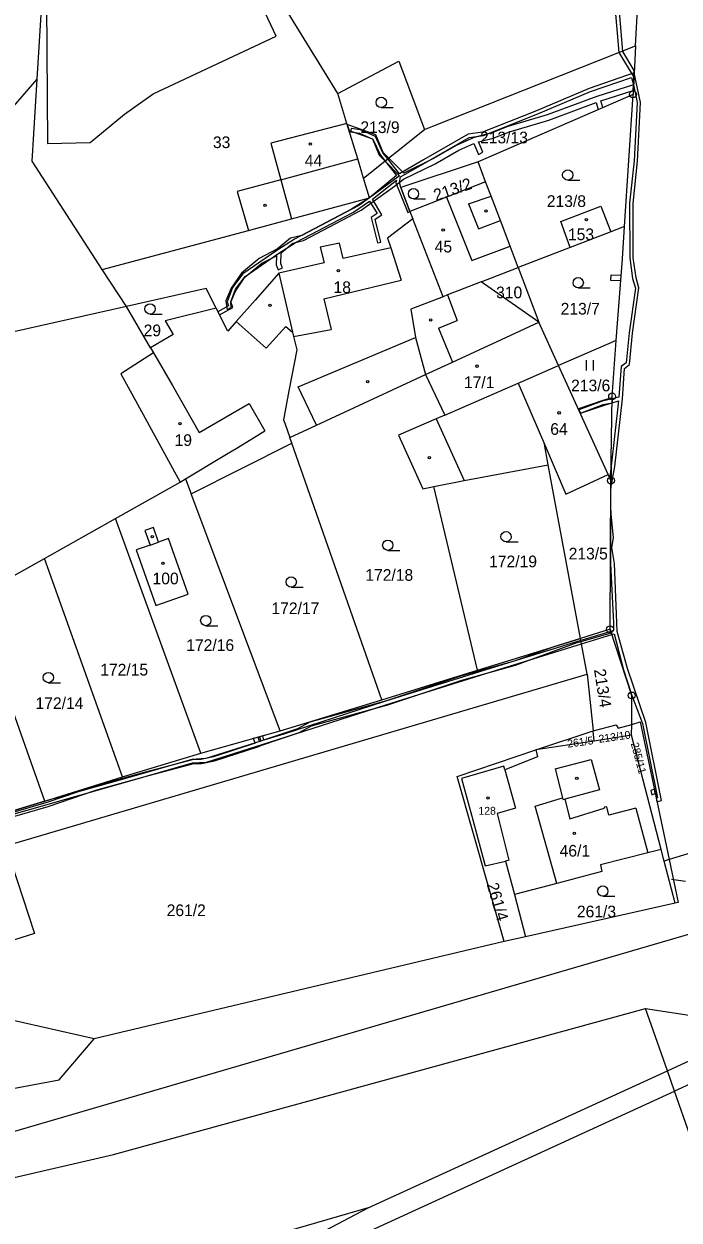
# Model space of a CAD drawing. Extents: x -779723 to -777378, y -1011169 to -1009297.
# Drawn here: x -779040.4 to -778945.2, y -1010475.7 to -1010301.7 of the extents above; entities that cross this region are included whole.
import ezdxf

# ---------------------------------------------------------------- set-up
doc = ezdxf.new("R2010")
doc.units = 0
for name, color, linetype in [('Hranice parcel', 7, 'Continuous'), ('Parcelní čísla', 7, 'Continuous'), ('Pop  PČ popisy', 7, 'Continuous'), ('Poz předměty', 7, 'Continuous'), ('Vnitřní kresba', 7, 'Continuous'), ('Věcná břemena k části', 7, 'Continuous'), ('Značky bodu BP', 7, 'Continuous'), ('Značky budov', 7, 'Continuous'), ('Značky kultur', 7, 'Continuous')]:
    doc.layers.add(name, color=color, linetype=linetype)

msp = doc.modelspace()

# ---------------------------------------------------------------- linework, layer by layer
at = {"layer": 'Hranice parcel'}
for p, q in [((-779038.46, -1010309.75), (-779037.78, -1010298.79)), ((-778951.52, -1010304.9), (-778951.89, -1010311.98)), ((-778993.45, -1010316.22), (-778994.79, -1010311.83)), ((-778951.89, -1010311.98), (-778974.4, -1010321.81)), ((-778953.14, -1010331.19), (-778951.89, -1010311.98)), ((-778991.02, -1010324.17), (-778982.17, -1010317.08)), ((-778973.3, -1010324.71), (-778974.4, -1010321.81)), ((-778962.38, -1010330.47), (-778956.54, -1010328.23)), ((-778956.54, -1010328.23), (-778955.13, -1010331.96)), ((-778984.3, -1010328.99), (-778983.88, -1010330.06)), ((-778979.48, -1010341.4), (-778983.88, -1010330.06)), ((-778961.01, -1010334.24), (-778962.38, -1010330.47)), ((-779028.99, -1010337.46), (-779007.73, -1010331.75)), ((-778955.13, -1010331.96), (-778961.01, -1010334.24)), ((-778953.14, -1010331.19), (-778955.13, -1010331.96)), ((-778961.01, -1010334.24), (-778968.56, -1010337.17)), ((-779025.5, -1010342.84), (-779028.99, -1010337.46)), ((-778973.94, -1010339.25), (-778968.56, -1010337.17)), ((-778968.56, -1010337.17), (-778965.56, -1010345.08)), ((-778965.56, -1010345.08), (-778973.94, -1010339.25)), ((-779025.5, -1010342.84), (-779071.49, -1010353.21)), ((-779021.98, -1010348.86), (-779025.5, -1010342.84)), ((-778962.69, -1010351.41), (-778965.56, -1010345.08)), ((-778954.32, -1010347.77), (-778962.69, -1010351.41)), ((-778955.49, -1010367.27), (-778962.69, -1010351.41)), ((-778982.04, -1010352.73), (-778979.24, -1010358.61)), ((-779001.48, -1010362.68), (-779001.76, -1010361.88)), ((-779016.08, -1010370.08), (-779001.48, -1010362.68)), ((-778988.37, -1010400.03), (-779001.48, -1010362.68)), ((-778959.52, -1010391.1), (-778964.2, -1010365.84)), ((-779027.09, -1010373.66), (-779017.69, -1010368.36)), ((-778955.1, -1010368.13), (-778955.49, -1010367.27)), ((-778955.22, -1010389.77), (-778955.1, -1010368.13)), ((-779003.14, -1010404.53), (-779016.08, -1010370.08)), ((-778974.46, -1010395.73), (-778980.82, -1010369)), ((-779037.39, -1010379.46), (-779027.09, -1010373.66)), ((-779014.66, -1010407.79), (-779027.09, -1010373.66)), ((-779047.78, -1010385.31), (-779037.39, -1010379.46)), ((-779026.05, -1010411.22), (-779037.39, -1010379.46)), ((-779037.35, -1010414.74), (-779047.78, -1010385.31)), ((-778955.22, -1010389.77), (-778959.52, -1010391.1)), ((-778974.46, -1010395.73), (-778959.52, -1010391.1)), ((-778958.54, -1010396.31), (-778959.52, -1010391.1)), ((-779043.02, -1010421.24), (-778958.54, -1010396.31)), ((-778988.37, -1010400.03), (-778974.46, -1010395.73)), ((-778958.54, -1010396.31), (-778957.7, -1010404.52)), ((-779003.14, -1010404.53), (-778988.37, -1010400.03)), ((-778952.09, -1010405.18), (-778952.08, -1010403.6)), ((-779014.66, -1010407.79), (-779003.14, -1010404.53)), ((-778966, -1010407.32), (-778957.7, -1010404.52)), ((-778957.55, -1010406.02), (-778957.7, -1010404.52)), ((-778952.09, -1010405.18), (-778957.55, -1010406.02)), ((-778947.8, -1010421.79), (-778952.09, -1010405.18)), ((-778957.55, -1010406.02), (-778966, -1010407.32)), ((-779026.05, -1010411.22), (-779014.66, -1010407.79)), ((-779037.35, -1010414.74), (-779026.05, -1010411.22)), ((-779048.8, -1010418.22), (-779037.35, -1010414.74)), ((-778947.37, -1010423.47), (-778947.8, -1010421.79)), ((-778970.41, -1010423.47), (-778969.13, -1010428.34)), ((-778946.64, -1010423.24), (-778947.37, -1010423.47)), ((-778945.78, -1010429.62), (-778947.37, -1010423.47)), ((-778969.13, -1010428.34), (-778967.51, -1010434.5)), ((-778945.78, -1010429.62), (-778967.51, -1010434.5)), ((-778967.51, -1010434.5), (-778970.59, -1010435.19)), ((-778970.59, -1010435.19), (-779030.17, -1010449.35)), ((-778950.06, -1010444.91), (-778942.45, -1010446.06)), ((-778946.9, -1010453.97), (-778950.06, -1010444.91)), ((-778990.37, -1010473.89), (-778946.9, -1010453.97)), ((-778945.86, -1010456.94), (-778946.9, -1010453.97)), ((-778927.24, -1010510.3), (-778945.86, -1010456.94)), ((-779003.19, -1010480.64), (-778990.37, -1010473.89))]:
    msp.add_line(p, q, dxfattribs=at)
for points in [[(-778951.52, -1010304.9), (-778950.58, -1010287.37), (-778950.58, -1010286.9), (-778950.34, -1010251.89), (-778953.35, -1010232.46), (-778955.45, -1010215), (-778962.68, -1010202.09), (-778972.6, -1010193.75), (-778987.54, -1010189.4), (-778999.84, -1010191.68), (-779009.45, -1010195.21), (-779017.34, -1010206.13), (-779023.92, -1010222.47), (-779024.96, -1010244.9), (-779026.78, -1010253.95)], [(-779037.1, -1010298.8), (-779036.94, -1010319.12), (-779030.77, -1010318.99), (-779025.76, -1010314.84), (-779021.61, -1010311.89), (-779003.74, -1010303.52), (-779004.9, -1010301.02), (-779009.89, -1010290.29)], [(-778994.79, -1010311.83), (-779008.43, -1010289.59), (-779009.89, -1010290.29)], [(-778982.17, -1010317.08), (-778980.98, -1010316.61), (-778951.52, -1010304.9)], [(-778994.79, -1010311.83), (-778985.9, -1010307.16), (-778982.17, -1010317.08)], [(-779058.85, -1010331.38), (-779053.49, -1010327.09), (-779038.46, -1010309.75)], [(-779028.99, -1010337.46), (-779039.2, -1010321.7), (-779038.46, -1010309.75)], [(-778993.45, -1010316.22), (-779004.53, -1010319.08), (-779003.07, -1010324.38), (-779009.39, -1010326.11), (-779007.73, -1010331.75)], [(-778991.02, -1010324.17), (-778991.89, -1010321.33), (-778993.45, -1010316.22)], [(-778974.4, -1010321.81), (-778985.64, -1010325.53), (-778984.3, -1010328.99)], [(-779007.73, -1010331.75), (-779001.5, -1010330.08), (-778990.15, -1010327.02), (-778991.02, -1010324.17)], [(-778973.3, -1010324.71), (-778978.98, -1010326.92), (-778984.3, -1010328.99)], [(-778968.56, -1010337.17), (-778969.74, -1010334.07), (-778971.16, -1010330.34), (-778972.52, -1010326.77), (-778973.3, -1010324.71)], [(-778983.88, -1010330.06), (-778987.54, -1010332.88), (-778987.09, -1010334.27), (-778994.02, -1010335.85), (-778994.52, -1010333.62), (-778997.34, -1010334.21), (-778996.76, -1010336.48), (-779003.36, -1010337.99)], [(-778954.32, -1010347.77), (-778953.44, -1010335.87), (-778953.14, -1010331.19)], [(-779003.36, -1010337.99), (-779006.8, -1010341.91), (-779009.52, -1010345.02), (-779010.76, -1010346.43), (-779012.47, -1010343.06)], [(-779003.36, -1010337.99), (-779001.36, -1010346.54), (-779001.2, -1010347.2), (-779000.74, -1010349.14), (-779001.87, -1010355.1), (-779002.67, -1010359.29), (-779002.49, -1010359.8), (-779001.76, -1010361.88)], [(-778973.94, -1010339.25), (-778977.19, -1010340.51), (-778978.84, -1010341.15), (-778979.48, -1010341.4)], [(-779012.47, -1010343.06), (-779013.91, -1010340.22), (-779025.5, -1010342.84)], [(-778979.48, -1010341.4), (-778984.19, -1010343.23), (-778983.47, -1010347.31), (-778982.04, -1010352.73)], [(-779012.47, -1010343.06), (-779019.86, -1010344.89), (-779018.7, -1010346.92), (-779021.98, -1010348.86)], [(-778955.1, -1010368.13), (-778954.92, -1010355.9), (-778954.32, -1010347.77)], [(-779021.98, -1010348.86), (-779021.56, -1010349.58), (-779026.3, -1010352.61), (-779023.89, -1010357.02), (-779017.69, -1010368.36)], [(-778979.24, -1010358.61), (-778968.59, -1010353.97), (-778967.89, -1010353.67), (-778962.69, -1010351.41)], [(-779001.76, -1010361.88), (-778997.87, -1010360.08), (-778982.04, -1010352.73)], [(-778979.24, -1010358.61), (-778980.51, -1010359.16), (-778985.96, -1010361.53), (-778982.41, -1010369.32), (-778980.82, -1010369)], [(-778964.2, -1010365.84), (-778964.75, -1010362.86), (-778961.63, -1010370.1), (-778955.49, -1010367.27)], [(-778980.82, -1010369), (-778976.43, -1010368.12), (-778964.2, -1010365.84)], [(-779017.69, -1010368.36), (-779016.89, -1010367.91), (-779016.08, -1010370.08)], [(-779022.06, -1010377.52), (-779024.08, -1010378.22), (-779021.2, -1010386.31), (-779016.52, -1010384.66), (-779019.35, -1010376.56), (-779020.82, -1010377.08), (-779021.54, -1010374.98), (-779022.8, -1010375.42), (-779022.06, -1010377.52)], [(-778952.08, -1010403.6), (-778952.07, -1010399.39), (-778955.22, -1010389.77)], [(-778957.7, -1010404.52), (-778954.34, -1010403.64), (-778954.03, -1010404.17), (-778952.08, -1010403.6)], [(-778952.08, -1010403.6), (-778950.86, -1010403.24), (-778946.64, -1010423.24)], [(-778970.59, -1010435.19), (-778977.43, -1010411.17), (-778966, -1010407.32)], [(-778966, -1010407.32), (-778965.76, -1010408.34), (-778970.52, -1010410.2)], [(-778970.52, -1010410.2), (-778970.66, -1010409.66), (-778976.79, -1010411.48), (-778975.16, -1010417.48), (-778973.38, -1010424.16), (-778970.41, -1010423.47)], [(-778970.52, -1010410.2), (-778968.98, -1010415.79), (-778971.61, -1010416.57), (-778969.93, -1010423.36), (-778970.41, -1010423.47)], [(-779043.02, -1010421.24), (-779038.86, -1010434.01), (-779059.85, -1010440.67), (-779063.54, -1010427.85)], [(-778947.8, -1010421.79), (-778949.74, -1010422.28), (-778956.63, -1010424.04), (-778956.41, -1010425.01), (-778962.94, -1010426.72), (-778969.13, -1010428.34)], [(-778934.57, -1010425.53), (-778941.48, -1010421.68), (-778946.64, -1010423.24)], [(-778946.64, -1010423.24), (-778945.31, -1010429.51), (-778945.78, -1010429.62)], [(-779161.4, -1010480.57), (-779135.21, -1010481.09), (-779105.39, -1010479.5), (-779067.56, -1010475.45), (-779027.37, -1010466.13), (-778950.06, -1010444.91)], [(-779030.17, -1010449.35), (-779043.03, -1010446.43), (-779084.08, -1010446.73), (-779168.06, -1010459.43)], [(-779165.75, -1010470.45), (-779127.38, -1010469.51), (-779070.54, -1010461.9), (-779035.24, -1010455.28), (-779030.17, -1010449.35)], [(-778946.9, -1010453.97), (-778941.12, -1010451.33), (-778940.34, -1010454.4), (-778945.86, -1010456.94)], [(-779019.86, -1010492.97), (-778990.5, -1010477.42), (-778945.86, -1010456.94)], [(-778990.37, -1010473.89), (-779005.39, -1010478.26), (-779064.14, -1010491.18), (-779114.77, -1010499.04), (-779160.87, -1010496.55)]]:
    msp.add_lwpolyline(points, dxfattribs=at)
at = {"layer": 'Pop  PČ popisy'}
msp.add_line((-778946.3, -1010426.12), (-778944.25, -1010426.4), dxfattribs=at)
at = {"layer": 'Poz předměty'}
msp.add_line((-779042.85, -1010463.08), (-778940.99, -1010433.26), dxfattribs=at)
at = {"layer": 'Vnitřní kresba'}
for p, q in [((-779003.07, -1010324.38), (-778991.89, -1010321.33)), ((-779003.07, -1010324.38), (-779001.5, -1010330.08)), ((-778978.98, -1010326.92), (-778975.29, -1010336.14)), ((-778975.77, -1010327.87), (-778972.52, -1010326.77)), ((-778975.77, -1010327.87), (-778974.32, -1010331.52)), ((-778974.32, -1010331.52), (-778971.16, -1010330.34)), ((-778975.29, -1010336.14), (-778969.74, -1010334.07)), ((-778987.09, -1010334.27), (-778985.56, -1010339)), ((-778996.79, -1010341.72), (-778985.56, -1010339)), ((-778996.79, -1010341.72), (-778995.73, -1010346.15)), ((-778978.84, -1010341.15), (-778977.42, -1010344.84)), ((-779009.52, -1010345.02), (-779005.2, -1010348.89)), ((-779005.2, -1010348.89), (-779002.31, -1010345.73)), ((-779002.31, -1010345.73), (-779001.36, -1010346.54)), ((-779001.2, -1010347.2), (-778995.73, -1010346.15)), ((-778980.14, -1010345.98), (-778977.42, -1010344.84)), ((-778980.14, -1010345.98), (-778978.1, -1010350.9)), ((-778970.99, -1010347.6), (-778965.56, -1010345.08)), ((-779000.55, -1010354.53), (-778983.47, -1010347.31)), ((-778978.1, -1010350.9), (-778970.99, -1010347.6)), ((-779021.56, -1010349.58), (-779018.79, -1010354.32)), ((-778982.04, -1010352.73), (-778978.1, -1010350.9)), ((-779018.79, -1010354.32), (-779014.92, -1010361.14)), ((-778997.87, -1010360.08), (-779000.55, -1010354.53)), ((-778968.59, -1010353.97), (-778964.75, -1010362.86)), ((-779014.92, -1010361.14), (-779007.64, -1010356.95)), ((-779007.64, -1010356.95), (-779005.36, -1010360.92)), ((-778980.51, -1010359.16), (-778976.43, -1010368.12)), ((-779009.32, -1010363.32), (-779005.36, -1010360.92)), ((-779011.17, -1010364.44), (-779009.32, -1010363.32)), ((-779016.89, -1010367.91), (-779011.17, -1010364.44)), ((-779022.06, -1010377.52), (-779020.82, -1010377.08)), ((-778963.18, -1010410.04), (-778957.95, -1010408.71)), ((-778957.95, -1010408.71), (-778956.78, -1010413.11)), ((-778963.18, -1010410.04), (-778962.15, -1010414.29)), ((-778956.78, -1010413.11), (-778961.8, -1010414.46)), ((-778966.1, -1010415.49), (-778962.15, -1010414.29)), ((-778962.94, -1010426.72), (-778966.1, -1010415.49)), ((-778962.15, -1010414.29), (-778962.09, -1010414.54)), ((-778962.09, -1010414.54), (-778961.8, -1010414.46)), ((-778961.8, -1010414.46), (-778961.07, -1010417.35)), ((-778961.07, -1010417.35), (-778956.08, -1010415.8)), ((-778955.71, -1010415.59), (-778956.1, -1010415.63)), ((-778956.1, -1010415.63), (-778956.08, -1010415.8)), ((-778955.41, -1010416.79), (-778955.71, -1010415.59)), ((-778951.46, -1010415.8), (-778955.41, -1010416.79)), ((-778951.46, -1010415.8), (-778949.74, -1010422.28))]:
    msp.add_line(p, q, dxfattribs=at)
at = {"layer": 'Věcná břemena k části'}
for points in [[(-778950.6, -1010287.72), (-778950.57, -1010286.48), (-778952.33, -1010289.54), (-778954.01, -1010291.89), (-778954.95, -1010294.05), (-778953.94, -1010305.88), (-778951.76, -1010309.46), (-778951.7, -1010308.5), (-778953.36, -1010305.72), (-778954.33, -1010294.15), (-778953.49, -1010292.19), (-778951.83, -1010289.86)], [(-778951.81, -1010310.57), (-778951.72, -1010308.85), (-778958.25, -1010311.12), (-778966.14, -1010314.45), (-778973.74, -1010317.48), (-778975.86, -1010317.76), (-778982.33, -1010321.49), (-778985.82, -1010323.51), (-778987.52, -1010321.36), (-778988.22, -1010320.47), (-778989.32, -1010318.12), (-778991.49, -1010317.14), (-778992.86, -1010316.95), (-778992.92, -1010317.44), (-778991.63, -1010317.62), (-778989.7, -1010318.5), (-778988.64, -1010320.73), (-778987.91, -1010321.68), (-778986.23, -1010323.79), (-778990.15, -1010327.02), (-778992.78, -1010328.66), (-779001.07, -1010333.01), (-779003.64, -1010334.66), (-779008.59, -1010338.09), (-779010.06, -1010340.05), (-779010.83, -1010342.13), (-779010.64, -1010342.73), (-779012.19, -1010343.61), (-779011.96, -1010344.06), (-779010.04, -1010342.97), (-779010.31, -1010342.15), (-779009.62, -1010340.29), (-779008.23, -1010338.45), (-779003.36, -1010335.08), (-779000.81, -1010333.45), (-778992.52, -1010329.1), (-778990.15, -1010327.52), (-778989.05, -1010329.31), (-778989.92, -1010329.88), (-778988.99, -1010333.58), (-778988.51, -1010333.46), (-778989.34, -1010330.1), (-778988.37, -1010329.47), (-778989.74, -1010327.23), (-778986.27, -1010324.46), (-778986.35, -1010324.84), (-778984.59, -1010329.14), (-778984.3, -1010328.99), (-778985.64, -1010325.53), (-778985.83, -1010324.8), (-778985.66, -1010323.99), (-778982.08, -1010321.92), (-778975.7, -1010318.24), (-778973.62, -1010317.96), (-778965.95, -1010314.91), (-778958.07, -1010311.58), (-778952.1, -1010309.51)], [(-778951.81, -1010310.57), (-778951.3, -1010313.18), (-778951.72, -1010321.64), (-778952.39, -1010327.82), (-778952.34, -1010335.76), (-778951.95, -1010338.74), (-778951.55, -1010340.15), (-778952.45, -1010346.64), (-778952.86, -1010351.01), (-778953.6, -1010351.56), (-778953.93, -1010356.01), (-778954.93, -1010356.24), (-778954.93, -1010356.85), (-778953.98, -1010356.53), (-778955.07, -1010366.03), (-778955.07, -1010366.37), (-778955.11, -1010369.23), (-778954.52, -1010366.11), (-778953.44, -1010356.23), (-778953.12, -1010351.82), (-778952.38, -1010351.27), (-778951.96, -1010346.7), (-778951.05, -1010340.11), (-778951.45, -1010338.64), (-778951.85, -1010335.73), (-778951.89, -1010327.84), (-778951.23, -1010321.68), (-778950.8, -1010313.14), (-778951.72, -1010308.85)], [(-778951.86, -1010311.41), (-778951.81, -1010310.57), (-778957.14, -1010312.27), (-778964.34, -1010314.96), (-778970.06, -1010316.64), (-778972.41, -1010317.59), (-778974.95, -1010318.23), (-778977.5, -1010319.37), (-778980.96, -1010321.37), (-778985.2, -1010323.44), (-778987.37, -1010321.25), (-778988.17, -1010320.44), (-778989.23, -1010317.87), (-778993.4, -1010316.38), (-778993.15, -1010317.22), (-778989.75, -1010318.43), (-778988.77, -1010320.8), (-778987.91, -1010321.68), (-778985.82, -1010323.81), (-778986.93, -1010324.67), (-778990.15, -1010327.02), (-778991.73, -1010328.12), (-779000, -1010332.48), (-779001.64, -1010332.9), (-779003.52, -1010334.46), (-779006.18, -1010335.82), (-779008.78, -1010337.99), (-779010.26, -1010340.16), (-779011.03, -1010342.02), (-779010.83, -1010343.3), (-779010.27, -1010342.92), (-779010.32, -1010342.18), (-779009.66, -1010340.6), (-779008.28, -1010338.58), (-779005.81, -1010336.52), (-779003.7, -1010335.44), (-779003.74, -1010336.76), (-779003.45, -1010337.49), (-779002.81, -1010337.18), (-779003.04, -1010336.62), (-779002.99, -1010335.02), (-779001.33, -1010333.63), (-778999.75, -1010333.23), (-778991.39, -1010328.82), (-778986.54, -1010325.33), (-778985.21, -1010324.31), (-778980.65, -1010322.08), (-778977.19, -1010320.11), (-778975, -1010319.12), (-778974.32, -1010320.72), (-778973.7, -1010320.39), (-778974.33, -1010318.9), (-778972.21, -1010318.36), (-778969.83, -1010317.41), (-778964.12, -1010315.73), (-778957.24, -1010313.16), (-778956.93, -1010314.18), (-778956.29, -1010313.9), (-778956.58, -1010312.93)], [(-778953.67, -1010339.03), (-778953.62, -1010338.33), (-778955.13, -1010338.28), (-778955.15, -1010338.98)], [(-778955.91, -1010357.11), (-778954.93, -1010356.85), (-778954.92, -1010356.12), (-778956.11, -1010356.44), (-778959.83, -1010357.7), (-778959.54, -1010358.35)], [(-778954.93, -1010356.85), (-778954.93, -1010356.24), (-778956.37, -1010356.58), (-778959.78, -1010357.83), (-778959.54, -1010358.35), (-778956.23, -1010357.06)], [(-778955.1, -1010368.13), (-778955.07, -1010366.37), (-778955.32, -1010367.66)], [(-778948.41, -1010414.84), (-778947.75, -1010414.66), (-778950.03, -1010403.32), (-778952.7, -1010395.48), (-778954.19, -1010390.08), (-778954.23, -1010388.81), (-778954.6, -1010380.19), (-778954.98, -1010377.89), (-778954.73, -1010376.46), (-778955.12, -1010372.49), (-778955.15, -1010376.44), (-778955.17, -1010380.25), (-778954.72, -1010388.82), (-778954.7, -1010389.94), (-778955.12, -1010390.07), (-778954.97, -1010390.54), (-778954.61, -1010390.43), (-778953.29, -1010395.66), (-778952.07, -1010399.39), (-778950.51, -1010403.45), (-778948.33, -1010414.3), (-778948.52, -1010414.35)], [(-778949.16, -1010413.82), (-778948.67, -1010413.64), (-778948.79, -1010413.04), (-778949.28, -1010413.23)]]:
    msp.add_lwpolyline(points, close=True, dxfattribs=at)
for points in [[(-779046.91, -1010418.45), (-779036.85, -1010415.56), (-779029.92, -1010413.18), (-779022.74, -1010411.18), (-779015.68, -1010409.29), (-779014.6, -1010409.28), (-779012.68, -1010408.91), (-779006.27, -1010406.8), (-779005.94, -1010406.67), (-779000.37, -1010404.78), (-778998.61, -1010403.83), (-778987.53, -1010400.74), (-778976.78, -1010397.17), (-778968.97, -1010394.97), (-778959.99, -1010391.71), (-778959.44, -1010391.55), (-778955.06, -1010390.27), (-778955.22, -1010389.77), (-778959.52, -1010391.1), (-778963.4, -1010392.3), (-778969.15, -1010394.39), (-778976.96, -1010396.59), (-778987.71, -1010400.16), (-778998.83, -1010403.27), (-779000.61, -1010404.22), (-779006.14, -1010406.11), (-779006.37, -1010405.44), (-779007.05, -1010405.64), (-779006.8, -1010406.35), (-779012.84, -1010408.33), (-779014.66, -1010408.68), (-779015.76, -1010408.69), (-779022.9, -1010410.6), (-779030.1, -1010412.6), (-779037.03, -1010414.98), (-779046.65, -1010417.75)], [(-779046.94, -1010418.07), (-779025.61, -1010411.99), (-779015.88, -1010409.21), (-779013.87, -1010409.07), (-779005.6, -1010406.46), (-779002.44, -1010405.47), (-778987.82, -1010400.76), (-778973.29, -1010396.19), (-778959.37, -1010391.9), (-778954.97, -1010390.54), (-778955.12, -1010390.07), (-778959.46, -1010391.41), (-778973.44, -1010395.72), (-778987.98, -1010400.28), (-779002.6, -1010405), (-779005.5, -1010405.91), (-779005.69, -1010405.25), (-779006.17, -1010405.39), (-779005.98, -1010406.06), (-779013.97, -1010408.57), (-779015.96, -1010408.71), (-779025.75, -1010411.51), (-779037.35, -1010414.74), (-779046.65, -1010417.57)]]:
    msp.add_lwpolyline(points, dxfattribs=at)
at = {"layer": 'Značky bodu BP'}
for centre, radius in [((-778951.89, -1010311.98), 0.5), ((-778951.89, -1010311.98), 0.0303), ((-778954.92, -1010355.9), 0.5), ((-778954.92, -1010355.9), 0.0303), ((-778955.1, -1010368.13), 0.5), ((-778955.1, -1010368.13), 0.0303), ((-778955.22, -1010389.77), 0.5), ((-778955.22, -1010389.77), 0.0303), ((-778952.07, -1010399.39), 0.5), ((-778952.07, -1010399.39), 0.0303)]:
    msp.add_circle(centre, radius, dxfattribs=at)
at = {"layer": 'Značky budov'}
for centre in [(-778998.77, -1010319.2), (-779005.35, -1010328.1), (-778973.26, -1010328.93), (-778958.67, -1010330.2), (-778979.47, -1010331.7), (-778994.7, -1010337.62), (-779004.61, -1010342.65), (-778981.28, -1010344.78), (-778974.55, -1010351.5), (-778990.43, -1010353.75), (-778962.62, -1010358.29), (-779017.69, -1010359.85), (-778981.47, -1010364.79), (-779021.74, -1010376.29), (-779020.19, -1010380.17), (-778960.05, -1010411.46), (-778972.94, -1010414.29), (-778960.43, -1010419.46)]:
    msp.add_circle(centre, 0.175, dxfattribs=at)
at = {"layer": 'Značky kultur'}
for p, q in [((-778988.46, -1010313.89), (-778986.71, -1010313.89)), ((-778961.37, -1010324.45), (-778959.62, -1010324.45)), ((-778983.78, -1010327.17), (-778982.03, -1010327.17)), ((-778959.85, -1010340.11), (-778958.1, -1010340.11)), ((-779022.06, -1010343.93), (-779020.31, -1010343.93)), ((-778958.65, -1010352.14), (-778958.65, -1010350.64)), ((-778957.65, -1010352.14), (-778957.65, -1010350.64)), ((-778970.34, -1010377.05), (-778968.59, -1010377.05)), ((-778987.52, -1010378.29), (-778985.77, -1010378.29)), ((-779001.55, -1010383.64), (-778999.8, -1010383.64)), ((-779013.96, -1010389.25), (-779012.21, -1010389.25)), ((-779036.83, -1010397.54), (-779035.08, -1010397.54)), ((-778956.28, -1010428.59), (-778954.53, -1010428.59))]:
    msp.add_line(p, q, dxfattribs=at)
for centre in [(-778988.46, -1010313.14), (-778961.37, -1010323.7), (-778983.78, -1010326.42), (-778959.85, -1010339.36), (-779022.06, -1010343.18), (-778970.34, -1010376.3), (-778987.52, -1010377.54), (-779001.55, -1010382.89), (-779013.96, -1010388.5), (-779036.83, -1010396.79), (-778956.28, -1010427.84)]:
    msp.add_circle(centre, 0.75, dxfattribs=at)

# ---------------------------------------------------------------- texts
at = {"layer": 'Parcelní čísla'}
for s, height, p in [('213/9', 1.7, (-778991.49, -1010317.6)), ('33', 1.7, (-779012.92, -1010319.79)), ('213/13', 1.7, (-778974.11, -1010319.1)), ('44', 1.7, (-778999.58, -1010322.46)), ('213/8', 1.7, (-778964.41, -1010328.35)), ('153', 1.7, (-778961.34, -1010333.18)), ('45', 1.7, (-778980.7, -1010334.96)), ('18', 1.7, (-778995.4, -1010340.87)), ('310', 1.7, (-778971.78, -1010341.63)), ('213/7', 1.7, (-778962.4, -1010344)), ('29', 1.7, (-779022.99, -1010347.15)), ('17/1', 1.7, (-778976.45, -1010354.7)), ('213/6', 1.7, (-778960.88, -1010355.16)), ('64', 1.7, (-778963.91, -1010361.49)), ('19', 1.7, (-779018.49, -1010363.11)), ('172/19', 1.7, (-778972.79, -1010380.75)), ('213/5', 1.7, (-778961.24, -1010379.61)), ('172/18', 1.7, (-778990.78, -1010382.72)), ('100', 1.7, (-779021.69, -1010383.23)), ('172/17', 1.7, (-779004.41, -1010387.56)), ('172/16', 1.7, (-779016.79, -1010392.92)), ('172/15', 1.7, (-779029.29, -1010396.49)), ('172/14', 1.7, (-779038.69, -1010401.37)), ('128', 1.139, (-778974.35, -1010416.73)), ('46/1', 1.7, (-778962.55, -1010422.83)), ('261/2', 1.7, (-779019.64, -1010431.48)), ('261/3', 1.7, (-778960.04, -1010431.66))]:
    msp.add_text(s, height=height, dxfattribs=at).set_placement(p)
for s, height, rotation, p in [('213/2', 1.7, 19, (-778980.52, -1010327.51)), ('213/4', 1.7, 279, (-778957.57, -1010395.65)), ('261/5', 1.139, 8, (-778961.35, -1010406.99)), ('213/10', 1.139, 8, (-778956.8, -1010406.29)), ('285/11', 1.139, 285, (-778952.22, -1010406.39)), ('261/4', 1.7, 286, (-778973.15, -1010426.88))]:
    msp.add_text(s, height=height, rotation=rotation, dxfattribs=at).set_placement(p)

doc.saveas('drawing.dxf')
